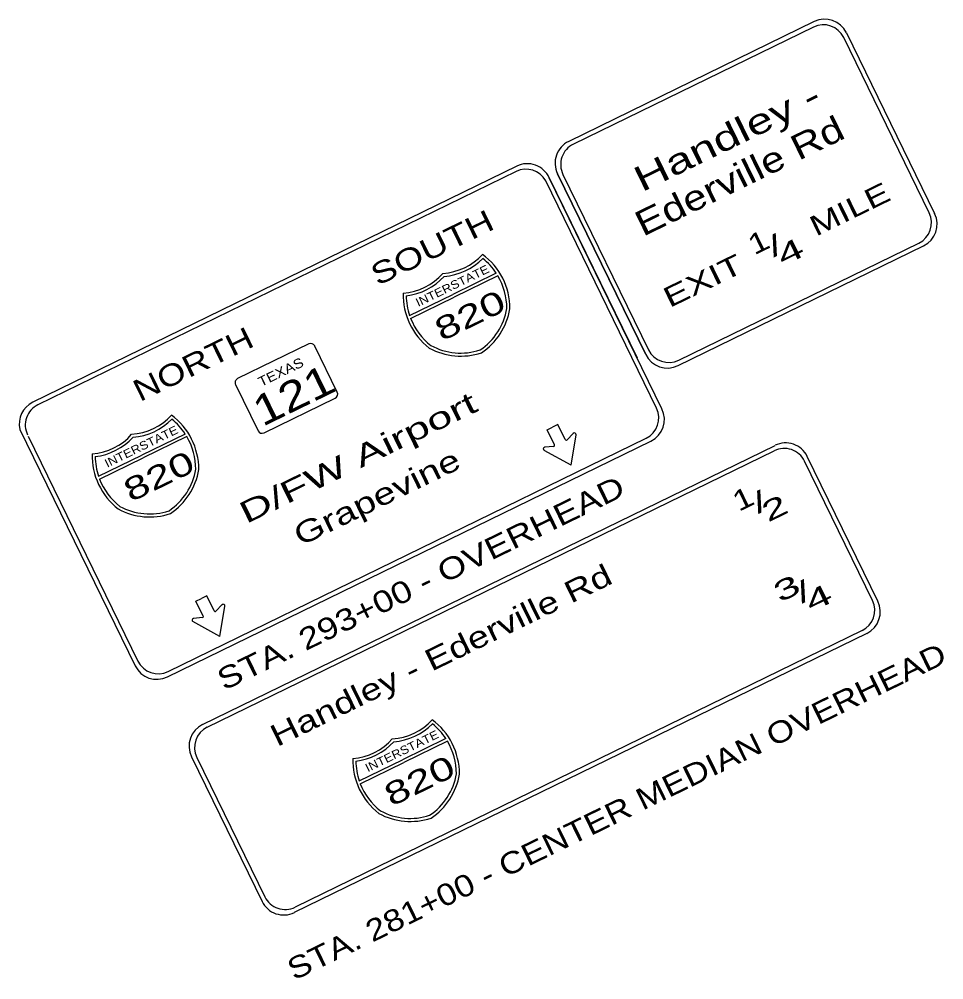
# Model space of a CAD drawing. Extents: x 2356431 to 2371438, y 6972864 to 6982525.
# Drawn here: x 2367270 to 2367845, y 6981928 to 6982525 of the extents above; entities that cross this region are included whole.
import ezdxf
from ezdxf.enums import TextEntityAlignment as Align

# ---------------------------------------------------------------- set-up
doc = ezdxf.new("R2010")
doc.units = 0
doc.header["$LTSCALE"] = 5.6
doc.layers.add('48', color=7, linetype='Continuous', lineweight=25)

msp = doc.modelspace()

# ---------------------------------------------------------------- linework, layer by layer
at = {"layer": '48'}
for p, q in [((2367764.511, 6982523.918), (2367611.739, 6982449.391)), ((2367764.044, 6982520.558), (2367614.661, 6982447.687)), ((2367784.625, 6982517.001), (2367839.501, 6982404.506)), ((2367836.134, 6982404.949), (2367782.907, 6982514.058)), ((2367579.439, 6982434.007), (2367278.185, 6982287.052)), ((2367578.996, 6982430.669), (2367281.446, 6982285.509)), ((2367666.438, 6982283.442), (2367597.464, 6982424.835)), ((2367604.801, 6982429.275), (2367659.677, 6982316.782)), ((2367608.176, 6982428.818), (2367661.403, 6982319.709)), ((2367679.812, 6982309.856), (2367832.561, 6982384.369)), ((2367680.263, 6982313.202), (2367829.648, 6982386.079)), ((2367566.673, 6982367.367), (2367539.717, 6982354.22)), ((2367567.674, 6982365.746), (2367540.545, 6982352.512)), ((2367512.745, 6982341.059), (2367539.717, 6982354.22)), ((2367513.394, 6982339.263), (2367540.545, 6982352.512)), ((2367449.94, 6982323.355), (2367405.69, 6982301.77)), ((2367467.697, 6982293.365), (2367453.7, 6982322.066)), ((2367404.392, 6982298.011), (2367418.397, 6982269.318)), ((2367422.158, 6982268.018), (2367466.401, 6982289.602)), ((2367270.162, 6982270.127), (2367341.922, 6982123.042)), ((2367598.289, 6982269.927), (2367601.683, 6982271.576)), ((2367602.845, 6982260.582), (2367598.289, 6982269.927)), ((2367605.077, 6982273.233), (2367601.683, 6982271.576)), ((2367609.633, 6982263.898), (2367605.077, 6982273.233)), ((2367275.326, 6982265.95), (2367343.616, 6982125.956)), ((2367373.08, 6982267.275), (2367346.124, 6982254.128)), ((2367374.081, 6982265.653), (2367346.952, 6982252.419)), ((2367362.427, 6982119.48), (2367659.978, 6982264.64)), ((2367610.741, 6982263.729), (2367614.584, 6982267.705)), ((2367613.252, 6982247.863), (2367616.302, 6982266.792)), ((2367361.977, 6982116.14), (2367662.89, 6982262.929)), ((2367383.918, 6982086.512), (2367740.162, 6982260.234)), ((2367613.252, 6982247.863), (2367596.467, 6982257.118)), ((2367602.311, 6982259.616), (2367596.797, 6982259.035)), ((2367319.152, 6982240.966), (2367346.124, 6982254.128)), ((2367319.801, 6982239.171), (2367346.952, 6982252.419)), ((2367386.831, 6982084.824), (2367739.681, 6982256.925)), ((2367804.144, 6982163.266), (2367760.202, 6982253.355)), ((2367800.798, 6982163.717), (2367758.498, 6982250.434)), ((2367379.731, 6982163.31), (2367383.116, 6982164.959)), ((2367384.281, 6982153.973), (2367379.731, 6982163.31)), ((2367386.519, 6982166.624), (2367383.116, 6982164.959)), ((2367391.067, 6982157.281), (2367386.519, 6982166.624)), ((2367392.174, 6982157.112), (2367396.019, 6982161.096)), ((2367394.686, 6982141.246), (2367397.737, 6982160.176)), ((2367394.686, 6982141.246), (2367377.902, 6982150.504)), ((2367383.755, 6982153.007), (2367378.24, 6982152.419)), ((2367794.314, 6982144.913), (2367441.449, 6981972.827)), ((2367797.229, 6982143.217), (2367440.992, 6981969.481)), ((2367535.302, 6982077.741), (2367508.346, 6982064.593)), ((2367536.298, 6982076.119), (2367509.176, 6982062.892)), ((2367377.009, 6982066.464), (2367420.951, 6981976.381)), ((2367380.362, 6982066.013), (2367422.655, 6981979.303)), ((2367481.391, 6982051.44), (2367508.346, 6982064.593)), ((2367482.038, 6982049.65), (2367509.176, 6982062.892))]:
    msp.add_line(p, q, dxfattribs=at)
for points in [[(2367669.799, 6982282.992), (2367599.639, 6982426.803), (2367654.319, 6982314.718)], [(2367659.473, 6982317.189), (2367604.801, 6982429.275), (2367659.481, 6982317.19)]]:
    msp.add_lwpolyline(points, dxfattribs=at)
for centre, radius, start, end in [((2367770.239, 6982507.881), 14.108, 26.00459, 116.00459), ((2367771.105, 6982510.397), 15.049, 26.00459, 116.00459), ((2367618.336, 6982435.871), 15.049, 116.00459, 206.00459), ((2367620.852, 6982435.005), 14.108, 116.00459, 206.00459), ((2367585.162, 6982418.024), 14.063, 28.96366, 116.00459), ((2367586.018, 6982420.528), 15.001, 24.72339, 116.00459), ((2367823.468, 6982398.767), 14.108, 296.00459, 26.00459), ((2367825.983, 6982397.901), 15.049, 296.00459, 26.00459), ((2367531.347, 6982403.175), 35.984, 273.18479, 318.0351), ((2367533.189, 6982345.358), 41.954, 359.86759, 53.56996), ((2367531.347, 6982403.175), 37.874, 274.3827, 315.37954), ((2367533.189, 6982345.358), 40.064, 33.31403, 51.17879), ((2367506.261, 6982390.938), 35.984, 273.9737, 318.82402), ((2367506.261, 6982390.938), 37.874, 276.62926, 317.6261), ((2367533.189, 6982345.358), 40.064, 0.08413, 30.59611), ((2367550.693, 6982353.897), 41.954, 178.43884, 232.14122), ((2367550.693, 6982353.897), 40.064, 180.83002, 198.69477), ((2367534.978, 6982351.83), 38.808, 303.84244, 350.48882), ((2367534.978, 6982351.83), 40.698, 303.4763, 350.7122), ((2367550.693, 6982353.897), 40.064, 201.4127, 231.92468), ((2367451.173, 6982320.836), 2.813, 26.00459, 116.00459), ((2367544.492, 6982356.47), 40.698, 241.29661, 288.53251), ((2367544.492, 6982356.47), 38.808, 241.51998, 288.16636), ((2367674.081, 6982325.891), 14.108, 206.00459, 296.00459), ((2367673.215, 6982323.376), 15.049, 206.00459, 296.00459), ((2367406.919, 6982299.247), 2.813, 116.00459, 206.00459), ((2367465.174, 6982292.136), 2.813, 296.00459, 26.00459), ((2367284.768, 6982273.567), 15.001, 116.00459, 193.23065), ((2367287.612, 6982272.868), 14.063, 116.00459, 206.00459), ((2367653.806, 6982277.275), 14.063, 296.00459, 26.00459), ((2367656.313, 6982276.412), 15.001, 296.00459, 26.00459), ((2367337.754, 6982303.082), 35.984, 273.18479, 318.0351), ((2367337.754, 6982303.082), 37.874, 274.3827, 315.37954), ((2367339.597, 6982245.265), 41.954, 359.86759, 53.56996), ((2367339.597, 6982245.265), 40.064, 33.31403, 51.17879), ((2367420.919, 6982270.547), 2.813, 206.00459, 296.00459), ((2367312.669, 6982290.845), 35.984, 273.9737, 318.82402), ((2367312.669, 6982290.845), 37.874, 276.62926, 317.6261), ((2367339.597, 6982245.265), 40.064, 0.08413, 30.59611), ((2367610.258, 6982264.182), 0.675, 206.00459, 315.9877), ((2367615.307, 6982266.99), 1.012, 350.74309, 136.12423), ((2367596.929, 6982258.024), 1.012, 95.88496, 241.2661), ((2367602.249, 6982260.276), 0.675, 276.02149, 26.00459), ((2367745.863, 6982244.265), 14.063, 26.00009, 116.00009), ((2367746.726, 6982246.772), 15.001, 26.00009, 116.00009), ((2367357.101, 6982253.804), 41.954, 178.43884, 232.14122), ((2367357.101, 6982253.804), 40.064, 180.83002, 198.69477), ((2367341.386, 6982251.737), 38.808, 303.84244, 350.48882), ((2367341.386, 6982251.737), 40.698, 303.4763, 350.7122), ((2367357.101, 6982253.804), 40.064, 201.4127, 231.92468), ((2367350.899, 6982256.378), 38.808, 241.51998, 288.16636), ((2367350.899, 6982256.378), 40.698, 241.29661, 288.53251), ((2367396.745, 6982160.376), 1.012, 350.74309, 136.12423), ((2367788.153, 6982157.552), 14.063, 296.00009, 26.00009), ((2367790.66, 6982156.689), 15.001, 296.00009, 26.00009), ((2367391.696, 6982157.568), 0.675, 206.00459, 315.9877), ((2367378.367, 6982151.41), 1.012, 95.88496, 241.2661), ((2367383.687, 6982153.662), 0.675, 276.02149, 26.00459), ((2367356.263, 6982132.122), 14.063, 206.00459, 296.00459), ((2367355.4, 6982129.614), 15.001, 206.00459, 296.00459), ((2367390.491, 6982073.041), 15.001, 115.99951, 205.99951), ((2367392.998, 6982072.178), 14.063, 115.99951, 205.99951), ((2367499.987, 6982113.533), 35.97, 273.18495, 318.03527), ((2367499.987, 6982113.533), 37.859, 274.38287, 315.37971), ((2367501.828, 6982055.739), 41.937, 359.86775, 53.57013), ((2367501.828, 6982055.739), 40.048, 33.3142, 51.17895), ((2367474.911, 6982101.3), 35.97, 273.97387, 318.82418), ((2367474.911, 6982101.3), 37.859, 276.62943, 317.62627), ((2367501.828, 6982055.739), 40.048, 0.08429, 30.59627), ((2367519.325, 6982064.274), 41.937, 178.43901, 232.14138), ((2367519.325, 6982064.274), 40.048, 180.83018, 198.69494), ((2367503.617, 6982062.207), 38.792, 303.84261, 350.48899), ((2367503.617, 6982062.207), 40.682, 303.47646, 350.71236), ((2367519.325, 6982064.274), 40.048, 201.41286, 231.92484), ((2367513.126, 6982066.846), 40.682, 241.29677, 288.53267), ((2367513.126, 6982066.846), 38.792, 241.52015, 288.16653), ((2367434.424, 6981982.957), 15.001, 205.99951, 295.99951), ((2367435.287, 6981985.464), 14.063, 205.99951, 295.99951)]:
    msp.add_arc(centre, radius, start, end, dxfattribs=at)

# ---------------------------------------------------------------- texts
for s, height, rotation, width, p in [('Handley -', 15.68, 26.005, 1.4, (2367713.756, 6982445.193)), ('Ederville Rd', 15.68, 26.005, 1.25, (2367721.443, 6982420.922)), ('MILE', 12.54, 26.005, 1.35, (2367789.401, 6982401.648)), ('SOUTH', 13.5, 26.005, 1.3, (2367529.689, 6982377.291)), ('1', 12.54, 26.005, 1.3, (2367732.639, 6982381.052)), ('/', 12.54, 26.005, 1.7, (2367742.837, 6982378.939)), ('4', 12.54, 26.005, 1.75, (2367752.308, 6982375.139)), ('EXIT', 12.54, 26.005, 1.4, (2367697.985, 6982357.054)), ('NORTH', 13.5, 26.005, 1.25, (2367380.945, 6982304.737)), ('D/FW Airport', 13.49, 26.005, 1.55, (2367483.607, 6982246.577)), ('Grapevine', 13.5, 26.005, 1.35, (2367495.341, 6982221.927)), ('STA. 293+00 - OVERHEAD', 13.5, 25.999, 1.25, (2367522.639, 6982168.553)), ('1', 12.54, 26, 1.3, (2367722.981, 6982221.39)), ('/', 12.54, 26, 1.7, (2367733.194, 6982219.274)), ('2', 12.54, 26, 1.65, (2367742.659, 6982215.487)), ('Handley - Ederville Rd', 13.5, 25.999, 1.3, (2367535.215, 6982123.59)), ('3', 12.54, 26, 1.7, (2367750.186, 6982165.641)), ('/', 12.54, 26, 1.7, (2367760.396, 6982163.526)), ('4', 12.54, 26, 1.75, (2367769.861, 6982159.737)), ('STA. 281+00 - CENTER MEDIAN OVERHEAD', 13.5, 25.999, 1.2, (2367644.541, 6982026.325))]:
    msp.add_text(s, height=height, rotation=rotation, dxfattribs=dict(at, width=width)).set_placement(p, align=Align.CENTER)
for s, height, rotation, width, p in [('INTERSTATE', 5.197, 26.004, 1.15, (2367518.086, 6982346.364)), ('820', 14.18, 26.004, 1.45, (2367532.779, 6982324.754)), ('TEXAS', 6, 26.005, 1.15, (2367420.293, 6982296.551)), ('121', 18.75, 26.005, 1.25, (2367421.146, 6982271.654)), ('INTERSTATE', 5.197, 26.004, 1.15, (2367324.494, 6982246.271)), ('820', 14.18, 26.004, 1.45, (2367339.186, 6982224.662)), ('INTERSTATE', 5.195, 26.005, 1.15, (2367486.729, 6982056.746)), ('820', 14.17, 26.005, 1.45, (2367501.415, 6982035.152))]:
    msp.add_text(s, height=height, rotation=rotation, dxfattribs=dict(at, width=width)).set_placement(p)

doc.saveas('drawing.dxf')
